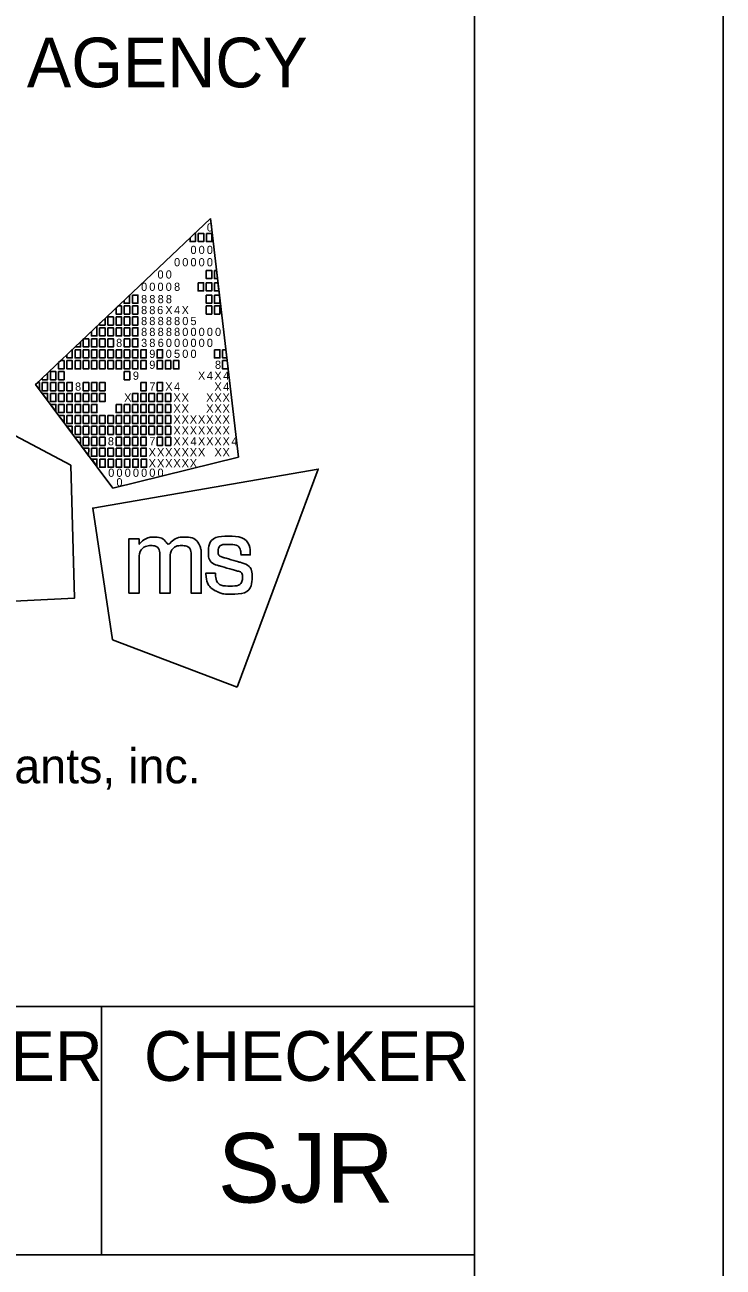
# Model space of a CAD drawing. Extents: x 0 to 34, y 0 to 22.
# Drawn here: x 32.596 to 34, y 2.475 to 4.976 of the extents above; entities that cross this region are included whole.
import ezdxf

# ---------------------------------------------------------------- set-up
doc = ezdxf.new("R2010")
doc.units = 0
for name, color, linetype in [('SH_Border', 7, 'Continuous'), ('SH_Cut_Line', 7, 'Continuous'), ('SH_Data', 7, 'Continuous'), ('SH_Text', 7, 'Continuous')]:
    doc.layers.add(name, color=color, linetype=linetype)

msp = doc.modelspace()

# ---------------------------------------------------------------- linework, layer by layer
at = {"layer": 'SH_Border'}
for p, q in [((32, 3), (33.5, 3)), ((32.75, 3), (32.75, 2.5)), ((32, 2.5), (33.5, 2.5))]:
    msp.add_line(p, q, dxfattribs=at)
msp.add_lwpolyline([(1.5, 21.5), (33.5, 21.5), (33.5, 0.5), (1.5, 0.5)], close=True, dxfattribs=at)
at = {"layer": 'SH_Cut_Line'}
msp.add_lwpolyline([(0, 0), (34, 0), (34, 22), (0, 22)], close=True, dxfattribs=at)
at = {"layer": 'SH_Data'}
msp.add_line((32.75, 4), (32.75, 4), dxfattribs=at)
at = {"layer": 'SH_Text'}
for p, q in [((32.6175, 4.2519), (32.9688, 4.5861)), ((32.9688, 4.5861), (32.9688, 4.5861)), ((32.9688, 4.5861), (33.0253, 4.1052)), ((32.773, 4.043), (32.6175, 4.2519)), ((33.0253, 4.1052), (32.773, 4.043))]:
    msp.add_line(p, q, dxfattribs=at)
for points in [[(32.9279, 4.5472), (32.9369, 4.5558), (32.9389, 4.5558), (32.9389, 4.5393), (32.9279, 4.5393)], [(32.9444, 4.5558), (32.9554, 4.5558), (32.9554, 4.5393), (32.9444, 4.5393)], [(32.9609, 4.5558), (32.9719, 4.5558), (32.9719, 4.5393), (32.9609, 4.5393)], [(32.9606, 4.4815), (32.9716, 4.4815), (32.9716, 4.465), (32.9606, 4.465)], [(32.9771, 4.4815), (32.9811, 4.4815), (32.983, 4.465), (32.9771, 4.465)], [(32.9441, 4.4567), (32.9551, 4.4567), (32.9551, 4.4402), (32.9441, 4.4402)], [(32.9606, 4.4567), (32.9716, 4.4567), (32.9716, 4.4402), (32.9606, 4.4402)], [(32.9771, 4.4567), (32.984, 4.4567), (32.9859, 4.4402), (32.9771, 4.4402)], [(32.7953, 4.4211), (32.8064, 4.4316), (32.8064, 4.4154), (32.7953, 4.4154)], [(32.8123, 4.4319), (32.8233, 4.4319), (32.8233, 4.4154), (32.8123, 4.4154)], [(32.9606, 4.4319), (32.9716, 4.4319), (32.9716, 4.4154), (32.9606, 4.4154)], [(32.9771, 4.4319), (32.9869, 4.4319), (32.9881, 4.4218), (32.9881, 4.4154), (32.9771, 4.4154)], [(32.7958, 4.4099), (32.8068, 4.4099), (32.8068, 4.3934), (32.7958, 4.3934)], [(32.8123, 4.4099), (32.8233, 4.4099), (32.8233, 4.3934), (32.8123, 4.3934)], [(32.9606, 4.4099), (32.9716, 4.4099), (32.9716, 4.3934), (32.9606, 4.3934)], [(32.9771, 4.4099), (32.9881, 4.4099), (32.9881, 4.3934), (32.9771, 4.3934)], [(32.7627, 4.3879), (32.7737, 4.3879), (32.7737, 4.3714), (32.7627, 4.3714)], [(32.7793, 4.3879), (32.7903, 4.3879), (32.7903, 4.3714), (32.7793, 4.3714)], [(32.7958, 4.3879), (32.8068, 4.3879), (32.8068, 4.3714), (32.7958, 4.3714)], [(32.8123, 4.3879), (32.8233, 4.3879), (32.8233, 4.3714), (32.8123, 4.3714)], [(32.7462, 4.3659), (32.7572, 4.3659), (32.7572, 4.3494), (32.7462, 4.3494)], [(32.7627, 4.3659), (32.7737, 4.3659), (32.7737, 4.3494), (32.7627, 4.3494)], [(32.7793, 4.3659), (32.7903, 4.3659), (32.7903, 4.3494), (32.7793, 4.3494)], [(32.7958, 4.3659), (32.8068, 4.3659), (32.8068, 4.3494), (32.7958, 4.3494)], [(32.8123, 4.3659), (32.8233, 4.3659), (32.8233, 4.3494), (32.8123, 4.3494)], [(32.7297, 4.3439), (32.7407, 4.3439), (32.7407, 4.3273), (32.7297, 4.3273)], [(32.7462, 4.3439), (32.7572, 4.3439), (32.7572, 4.3273), (32.7462, 4.3273)], [(32.7627, 4.3439), (32.7737, 4.3439), (32.7737, 4.3273), (32.7627, 4.3273)], [(32.7958, 4.3439), (32.8068, 4.3439), (32.8068, 4.3273), (32.7958, 4.3273)], [(32.8123, 4.3439), (32.8233, 4.3439), (32.8233, 4.3273), (32.8123, 4.3273)], [(32.6967, 4.3218), (32.7077, 4.3218), (32.7077, 4.3053), (32.6967, 4.3053)], [(32.7132, 4.3218), (32.7242, 4.3218), (32.7242, 4.3053), (32.7132, 4.3053)], [(32.7297, 4.3218), (32.7407, 4.3218), (32.7407, 4.3053), (32.7297, 4.3053)], [(32.7462, 4.3218), (32.7572, 4.3218), (32.7572, 4.3053), (32.7462, 4.3053)], [(32.7627, 4.3218), (32.7737, 4.3218), (32.7737, 4.3053), (32.7627, 4.3053)], [(32.7793, 4.3218), (32.7903, 4.3218), (32.7903, 4.3053), (32.7793, 4.3053)], [(32.7958, 4.3218), (32.8068, 4.3218), (32.8068, 4.3053), (32.7958, 4.3053)], [(32.8123, 4.3218), (32.8233, 4.3218), (32.8233, 4.3053), (32.8123, 4.3053)], [(32.8288, 4.3218), (32.8398, 4.3218), (32.8398, 4.3053), (32.8288, 4.3053)], [(32.8618, 4.3218), (32.8728, 4.3218), (32.8728, 4.3053), (32.8618, 4.3053)], [(32.9771, 4.3218), (32.9881, 4.3218), (32.9881, 4.3053), (32.9771, 4.3053)], [(32.9935, 4.3218), (32.9998, 4.3218), (33.0018, 4.3053), (32.9935, 4.3053)], [(32.6471, 4.2778), (32.6581, 4.2778), (32.6581, 4.2613), (32.6471, 4.2613)], [(32.6637, 4.2778), (32.6747, 4.2778), (32.6747, 4.2613), (32.6637, 4.2613)], [(32.6802, 4.2998), (32.6912, 4.2998), (32.6912, 4.2833), (32.6802, 4.2833)], [(32.6967, 4.2998), (32.7077, 4.2998), (32.7077, 4.2833), (32.6967, 4.2833)], [(32.7132, 4.2998), (32.7242, 4.2998), (32.7242, 4.2833), (32.7132, 4.2833)], [(32.7297, 4.2998), (32.7407, 4.2998), (32.7407, 4.2833), (32.7297, 4.2833)], [(32.7462, 4.2998), (32.7572, 4.2998), (32.7572, 4.2833), (32.7462, 4.2833)], [(32.7627, 4.2998), (32.7737, 4.2998), (32.7737, 4.2833), (32.7627, 4.2833)], [(32.7793, 4.2998), (32.7903, 4.2998), (32.7903, 4.2833), (32.7793, 4.2833)], [(32.7958, 4.2998), (32.8068, 4.2998), (32.8068, 4.2833), (32.7958, 4.2833)], [(32.7958, 4.2778), (32.8068, 4.2778), (32.8068, 4.2613), (32.7958, 4.2613)], [(32.8123, 4.2998), (32.8233, 4.2998), (32.8233, 4.2833), (32.8123, 4.2833)], [(32.8288, 4.2998), (32.8398, 4.2998), (32.8398, 4.2833), (32.8288, 4.2833)], [(32.8618, 4.2998), (32.8728, 4.2998), (32.8728, 4.2833), (32.8618, 4.2833)], [(32.8783, 4.2998), (32.8893, 4.2998), (32.8893, 4.2833), (32.8783, 4.2833)], [(32.8947, 4.2998), (32.9057, 4.2998), (32.9057, 4.2833), (32.8947, 4.2833)], [(32.9935, 4.2998), (33.0024, 4.2998), (33.0044, 4.2833), (32.9935, 4.2833)], [(32.6306, 4.2558), (32.6416, 4.2558), (32.6416, 4.2393), (32.6306, 4.2393)], [(32.6471, 4.2558), (32.6581, 4.2558), (32.6581, 4.2393), (32.6471, 4.2393)], [(32.6637, 4.2558), (32.6747, 4.2558), (32.6747, 4.2393), (32.6637, 4.2393)], [(32.6802, 4.2558), (32.6912, 4.2558), (32.6912, 4.2393), (32.6802, 4.2393)], [(32.7132, 4.2558), (32.7242, 4.2558), (32.7242, 4.2393), (32.7132, 4.2393)], [(32.7297, 4.2558), (32.7407, 4.2558), (32.7407, 4.2393), (32.7297, 4.2393)], [(32.7462, 4.2558), (32.7572, 4.2558), (32.7572, 4.2393), (32.7462, 4.2393)], [(32.8288, 4.2558), (32.8398, 4.2558), (32.8398, 4.2393), (32.8288, 4.2393)], [(32.8618, 4.2558), (32.8728, 4.2558), (32.8728, 4.2393), (32.8618, 4.2393)], [(32.6306, 4.2338), (32.6416, 4.2338), (32.6416, 4.22)], [(32.6471, 4.2338), (32.6581, 4.2338), (32.6581, 4.2173), (32.6471, 4.2173)], [(32.6637, 4.2338), (32.6747, 4.2338), (32.6747, 4.2173), (32.6637, 4.2173)], [(32.6802, 4.2338), (32.6912, 4.2338), (32.6912, 4.2173), (32.6802, 4.2173)], [(32.6967, 4.2338), (32.7077, 4.2338), (32.7077, 4.2173), (32.6967, 4.2173)], [(32.7132, 4.2338), (32.7242, 4.2338), (32.7242, 4.2173), (32.7132, 4.2173)], [(32.7297, 4.2338), (32.7407, 4.2338), (32.7407, 4.2173), (32.7297, 4.2173)], [(32.7462, 4.2338), (32.7572, 4.2338), (32.7572, 4.2173), (32.7462, 4.2173)], [(32.8123, 4.2338), (32.8233, 4.2338), (32.8233, 4.2173), (32.8123, 4.2173)], [(32.8288, 4.2338), (32.8398, 4.2338), (32.8398, 4.2173), (32.8288, 4.2173)], [(32.8453, 4.2338), (32.8563, 4.2338), (32.8563, 4.2173), (32.8453, 4.2173)], [(32.8618, 4.2338), (32.8728, 4.2338), (32.8728, 4.2173), (32.8618, 4.2173)], [(32.8783, 4.2338), (32.8893, 4.2338), (32.8893, 4.2173), (32.8783, 4.2173)], [(32.6471, 4.2117), (32.6581, 4.2117), (32.6581, 4.198)], [(32.6637, 4.2117), (32.6747, 4.2117), (32.6747, 4.1952), (32.6637, 4.1952)], [(32.6802, 4.2117), (32.6912, 4.2117), (32.6912, 4.1952), (32.6802, 4.1952)], [(32.6967, 4.2117), (32.7077, 4.2117), (32.7077, 4.1952), (32.6967, 4.1952)], [(32.7132, 4.2117), (32.7242, 4.2117), (32.7242, 4.1952), (32.7132, 4.1952)], [(32.7297, 4.2117), (32.7407, 4.2117), (32.7407, 4.1952), (32.7297, 4.1952)], [(32.7793, 4.2117), (32.7903, 4.2117), (32.7903, 4.1952), (32.7793, 4.1952)], [(32.7958, 4.2117), (32.8068, 4.2117), (32.8068, 4.1952), (32.7958, 4.1952)], [(32.8123, 4.2117), (32.8233, 4.2117), (32.8233, 4.1952), (32.8123, 4.1952)], [(32.8288, 4.2117), (32.8398, 4.2117), (32.8398, 4.1952), (32.8288, 4.1952)], [(32.8453, 4.2117), (32.8563, 4.2117), (32.8563, 4.1952), (32.8453, 4.1952)], [(32.8618, 4.2117), (32.8728, 4.2117), (32.8728, 4.1952), (32.8618, 4.1952)], [(32.8783, 4.2117), (32.8893, 4.2117), (32.8893, 4.1952), (32.8783, 4.1952)], [(32.6637, 4.1897), (32.6747, 4.1897), (32.6747, 4.176)], [(32.6747, 4.1897), (32.6747, 4.1897), (32.6747, 4.1897)], [(32.6802, 4.1897), (32.6912, 4.1897), (32.6912, 4.1732), (32.6802, 4.1732)], [(32.6967, 4.1897), (32.7077, 4.1897), (32.7077, 4.1732), (32.6967, 4.1732)], [(32.7132, 4.1897), (32.7242, 4.1897), (32.7242, 4.1732), (32.7132, 4.1732)], [(32.7297, 4.1897), (32.7407, 4.1897), (32.7407, 4.1732), (32.7297, 4.1732)], [(32.7462, 4.1897), (32.7572, 4.1897), (32.7572, 4.1732), (32.7462, 4.1732)], [(32.7627, 4.1897), (32.7737, 4.1897), (32.7737, 4.1732), (32.7627, 4.1732)], [(32.7793, 4.1897), (32.7903, 4.1897), (32.7903, 4.1732), (32.7793, 4.1732)], [(32.7958, 4.1897), (32.8068, 4.1897), (32.8068, 4.1732), (32.7958, 4.1732)], [(32.8123, 4.1897), (32.8233, 4.1897), (32.8233, 4.1732), (32.8123, 4.1732)], [(32.8288, 4.1897), (32.8398, 4.1897), (32.8398, 4.1732), (32.8288, 4.1732)], [(32.8453, 4.1897), (32.8563, 4.1897), (32.8563, 4.1732), (32.8453, 4.1732)], [(32.8618, 4.1897), (32.8728, 4.1897), (32.8728, 4.1732), (32.8618, 4.1732)], [(32.8783, 4.1897), (32.8893, 4.1897), (32.8893, 4.1732), (32.8783, 4.1732)], [(32.6802, 4.1677), (32.6912, 4.1677), (32.6912, 4.154)], [(32.6967, 4.1677), (32.7077, 4.1677), (32.7077, 4.1512), (32.6967, 4.1512)], [(32.7132, 4.1677), (32.7242, 4.1677), (32.7242, 4.1512), (32.7132, 4.1512)], [(32.7297, 4.1677), (32.7407, 4.1677), (32.7407, 4.1512), (32.7297, 4.1512)], [(32.7462, 4.1677), (32.7572, 4.1677), (32.7572, 4.1512), (32.7462, 4.1512)], [(32.7627, 4.1677), (32.7737, 4.1677), (32.7737, 4.1512), (32.7627, 4.1512)], [(32.7793, 4.1677), (32.7903, 4.1677), (32.7903, 4.1512), (32.7793, 4.1512)], [(32.7958, 4.1677), (32.8068, 4.1677), (32.8068, 4.1512), (32.7958, 4.1512)], [(32.8123, 4.1677), (32.8233, 4.1677), (32.8233, 4.1512), (32.8123, 4.1512)], [(32.8288, 4.1677), (32.8398, 4.1677), (32.8398, 4.1512), (32.8288, 4.1512)], [(32.8453, 4.1677), (32.8563, 4.1677), (32.8563, 4.1512), (32.8453, 4.1512)], [(32.8618, 4.1677), (32.8728, 4.1677), (32.8728, 4.1512), (32.8618, 4.1512)], [(32.8783, 4.1677), (32.8893, 4.1677), (32.8893, 4.1512), (32.8783, 4.1512)], [(32.7077, 4.1305), (32.6965, 4.1457), (32.7077, 4.1457)], [(32.7132, 4.1457), (32.7242, 4.1457), (32.7242, 4.1292), (32.7132, 4.1292)], [(32.7297, 4.1457), (32.7407, 4.1457), (32.7407, 4.1292), (32.7297, 4.1292)], [(32.7462, 4.1457), (32.7572, 4.1457), (32.7572, 4.1292), (32.7462, 4.1292)], [(32.7793, 4.1457), (32.7903, 4.1457), (32.7903, 4.1292), (32.7793, 4.1292)], [(32.7958, 4.1457), (32.8068, 4.1457), (32.8068, 4.1292), (32.7958, 4.1292)], [(32.8123, 4.1457), (32.8233, 4.1457), (32.8233, 4.1292), (32.8123, 4.1292)], [(32.8288, 4.1457), (32.8398, 4.1457), (32.8398, 4.1292), (32.8288, 4.1292)], [(32.8618, 4.1457), (32.8728, 4.1457), (32.8728, 4.1292), (32.8618, 4.1292)], [(32.8783, 4.1457), (32.8893, 4.1457), (32.8893, 4.1292), (32.8783, 4.1292)], [(32.724, 4.1082), (32.7132, 4.1237), (32.7242, 4.1237)], [(32.7297, 4.1237), (32.7407, 4.1237), (32.7407, 4.1072), (32.7297, 4.1072)], [(32.7302, 4.1017), (32.7407, 4.1017), (32.7408, 4.0875)], [(32.7462, 4.1237), (32.7572, 4.1237), (32.7572, 4.1072), (32.7462, 4.1072)], [(32.7463, 4.1017), (32.7573, 4.1017), (32.7573, 4.0852), (32.7463, 4.0852)], [(32.7627, 4.1237), (32.7737, 4.1237), (32.7737, 4.1072), (32.7627, 4.1072)], [(32.763, 4.1017), (32.774, 4.1017), (32.774, 4.0852), (32.763, 4.0852)], [(32.7793, 4.1237), (32.7903, 4.1237), (32.7903, 4.1072), (32.7793, 4.1072)], [(32.7794, 4.1017), (32.7904, 4.1017), (32.7904, 4.0852), (32.7794, 4.0852)], [(32.7958, 4.1237), (32.8068, 4.1237), (32.8068, 4.1072), (32.7958, 4.1072)], [(32.796, 4.1017), (32.807, 4.1017), (32.807, 4.0852), (32.796, 4.0852)], [(32.8123, 4.1237), (32.8233, 4.1237), (32.8233, 4.1072), (32.8123, 4.1072)], [(32.8129, 4.1017), (32.8239, 4.1017), (32.8239, 4.0851), (32.8129, 4.0851)], [(32.8288, 4.1237), (32.8398, 4.1237), (32.8398, 4.1072), (32.8288, 4.1072)], [(32.8296, 4.1017), (32.8406, 4.1017), (32.8406, 4.0851), (32.8296, 4.0851)]]:
    msp.add_lwpolyline(points, close=True, dxfattribs=at)
for points in [[(32.7903, 4.4099), (32.7836, 4.4099), (32.7793, 4.4058), (32.7793, 4.3934), (32.7903, 4.3934), (32.7903, 4.4099)], [(32.7572, 4.3849), (32.7462, 4.3744), (32.7462, 4.3714), (32.7572, 4.3714), (32.7572, 4.3849)], [(32.7407, 4.3691), (32.7297, 4.3587), (32.7297, 4.3494), (32.7407, 4.3494), (32.7407, 4.3691)], [(32.7077, 4.3377), (32.6968, 4.3273), (32.7077, 4.3273), (32.7077, 4.3377)], [(32.7242, 4.3439), (32.7141, 4.3439), (32.7132, 4.343), (32.7132, 4.3273), (32.7242, 4.3273), (32.7242, 4.3439)], [(32.6912, 4.322), (32.6802, 4.3115), (32.6802, 4.3053), (32.6912, 4.3053), (32.6912, 4.322)], [(32.6747, 4.2998), (32.6679, 4.2998), (32.6637, 4.2958), (32.6637, 4.2833), (32.6747, 4.2833), (32.6747, 4.2998)], [(32.6251, 4.2558), (32.6216, 4.2558), (32.6175, 4.2519), (32.6251, 4.2417), (32.6251, 4.2558)], [(32.6416, 4.2749), (32.6306, 4.2644), (32.6306, 4.2613), (32.6416, 4.2613), (32.6416, 4.2749)], [(32.4512, 4.2149), (32.2359, 3.7988), (32.6956, 3.8215), (32.6884, 4.0892), (32.4512, 4.2149)], [(33.0229, 3.6422), (33.1859, 4.0814), (32.7324, 4.0029), (32.7722, 3.7381), (33.0229, 3.6422)]]:
    msp.add_lwpolyline(points, dxfattribs=at)
for points in [[(32.8048, 3.8315), (32.8048, 3.8315), (32.8048, 3.9409), (32.8048, 3.9409), (32.8048, 3.9409), (32.8255, 3.9409), (32.8255, 3.9409), (32.8255, 3.9409), (32.8255, 3.9297), (32.8255, 3.9297), (32.8346, 3.9399), (32.8457, 3.9445), (32.8555, 3.9445), (32.8688, 3.9445), (32.8791, 3.9372), (32.8837, 3.9266), (32.8915, 3.9381), (32.905, 3.9446), (32.9166, 3.9446), (32.9325, 3.9446), (32.9451, 3.935), (32.9494, 3.9213), (32.9494, 3.9212), (32.9494, 3.9212), (32.9494, 3.9212), (32.9501, 3.919), (32.9506, 3.9172), (32.9506, 3.9071), (32.9506, 3.9071), (32.9506, 3.8314), (32.9506, 3.8314), (32.9506, 3.8314), (32.9303, 3.8314), (32.9303, 3.8314), (32.9303, 3.8314), (32.9303, 3.9048), (32.9303, 3.9048), (32.9303, 3.9201), (32.9219, 3.9274), (32.911, 3.9274), (32.8995, 3.9274), (32.8879, 3.9171), (32.8879, 3.9001), (32.8879, 3.9001), (32.8879, 3.8315), (32.8879, 3.8315), (32.8879, 3.8315), (32.8674, 3.8315), (32.8674, 3.8315), (32.8674, 3.8315), (32.8674, 3.9059), (32.8674, 3.9059), (32.8674, 3.9203), (32.8588, 3.9274), (32.8496, 3.9274), (32.8384, 3.9274), (32.8254, 3.917), (32.8254, 3.8962), (32.8254, 3.8962), (32.8254, 3.8315), (32.8254, 3.8315), (32.8254, 3.8315), (32.8048, 3.8315), (32.8048, 3.8315)], [(32.9595, 3.8709), (32.9595, 3.8709), (32.9595, 3.8717), (32.9595, 3.8717), (32.9595, 3.8717), (32.9603, 3.8717), (32.9603, 3.8717), (32.9603, 3.8717), (32.9783, 3.8717), (32.9783, 3.8717), (32.9783, 3.8717), (32.9789, 3.8717), (32.9789, 3.8717), (32.9789, 3.8717), (32.979, 3.871), (32.979, 3.871), (32.9803, 3.8554), (32.9887, 3.846), (33.009, 3.846), (33.0273, 3.846), (33.0333, 3.8554), (33.0333, 3.8631), (33.0333, 3.8732), (33.0256, 3.8758), (33.0175, 3.878), (33.0175, 3.878), (32.987, 3.8867), (32.987, 3.8867), (32.972, 3.8909), (32.9648, 3.9019), (32.9648, 3.9142), (32.9648, 3.9303), (32.9768, 3.9462), (33.0052, 3.9462), (33.0348, 3.9462), (33.0489, 3.9285), (33.0489, 3.9095), (33.0489, 3.9095), (33.0489, 3.9087), (33.0489, 3.9087), (33.0489, 3.9087), (33.0482, 3.9087), (33.0482, 3.9087), (33.0482, 3.9087), (33.0312, 3.9087), (33.0312, 3.9087), (33.0312, 3.9087), (33.0305, 3.9087), (33.0305, 3.9087), (33.0305, 3.9087), (33.0305, 3.9094), (33.0305, 3.9094), (33.0301, 3.9208), (33.0226, 3.93), (33.0056, 3.93), (32.9891, 3.93), (32.9843, 3.9218), (32.9843, 3.9157), (32.9843, 3.9108), (32.9869, 3.9059), (32.9959, 3.9033), (32.9959, 3.9033), (33.0255, 3.8948), (33.0255, 3.8948), (33.0462, 3.8889), (33.0527, 3.8777), (33.0527, 3.8639), (33.0527, 3.8462), (33.041, 3.8298), (33.0087, 3.8298), (32.9952, 3.8298), (32.9877, 3.8321), (32.9823, 3.8348), (32.969, 3.8414), (32.9609, 3.8536), (32.9595, 3.8709)]]:
    msp.add_open_spline(points, degree=3, dxfattribs=at)

# ---------------------------------------------------------------- texts
at = {"layer": 'SH_Border'}
msp.add_text('ms consultants, inc.', height=0.07, rotation=360, dxfattribs=at).set_placement((32.1273, 3.4489))
at = {"layer": 'SH_Data'}
for s, height, p in [('DESIGN AGENCY', 0.1, (32.05, 4.85)), ('DESIGNER', 0.1, (32.054, 2.85)), ('CHECKER', 0.1, (32.8352, 2.85)), ('SJR', 0.14, (32.9839, 2.605))]:
    msp.add_text(s, height=height, dxfattribs=at).set_placement(p)
at = {"layer": 'SH_Text'}
for s, p in [('0', (32.9617, 4.5597)), ('0', (32.9288, 4.5145)), ('0', (32.9452, 4.5145)), ('0', (32.9617, 4.5145)), ('0', (32.8958, 4.4897)), ('0', (32.9123, 4.4897)), ('0', (32.9288, 4.4897)), ('0', (32.9452, 4.4897)), ('0', (32.9617, 4.4897)), ('0', (32.8625, 4.465)), ('0', (32.879, 4.465)), ('0', (32.8295, 4.4402)), ('0', (32.846, 4.4402)), ('0', (32.8625, 4.4402)), ('0', (32.879, 4.4402)), ('8', (32.8958, 4.4402)), ('8', (32.8295, 4.4154)), ('8', (32.846, 4.4154)), ('8', (32.8628, 4.4154)), ('8', (32.8793, 4.4154)), ('8', (32.8295, 4.3934)), ('8', (32.846, 4.3934)), ('6', (32.8618, 4.3934)), ('X', (32.8781, 4.3934)), ('4', (32.8958, 4.3934)), ('X', (32.911, 4.3934)), ('8', (32.8295, 4.3713)), ('8', (32.846, 4.3713)), ('8', (32.8628, 4.3713)), ('8', (32.8794, 4.3713)), ('8', (32.8958, 4.3713)), ('0', (32.9123, 4.3713)), ('5', (32.9287, 4.3713)), ('8', (32.8295, 4.3494)), ('8', (32.846, 4.3494)), ('8', (32.8628, 4.3494)), ('8', (32.8794, 4.3494)), ('8', (32.8958, 4.3494)), ('0', (32.9123, 4.3494)), ('0', (32.9288, 4.3494)), ('0', (32.9452, 4.3494)), ('0', (32.9617, 4.3494)), ('0', (32.9782, 4.3494)), ('8', (32.7793, 4.3273)), ('3', (32.8295, 4.3273)), ('8', (32.846, 4.3273)), ('6', (32.8629, 4.3273)), ('0', (32.8793, 4.3273)), ('0', (32.8958, 4.3273)), ('0', (32.9123, 4.3273)), ('0', (32.9288, 4.3273)), ('0', (32.9452, 4.3273)), ('0', (32.9617, 4.3273)), ('9', (32.846, 4.3053)), ('0', (32.879, 4.3053)), ('5', (32.8957, 4.3053)), ('0', (32.9123, 4.3053)), ('0', (32.9288, 4.3053)), ('9', (32.813, 4.2613)), ('9', (32.846, 4.2833)), ('X', (32.9439, 4.2613)), ('4', (32.9617, 4.2613)), ('X', (32.9769, 4.2613)), ('8', (32.9781, 4.2833)), ('4', (32.9946, 4.2613)), ('8', (32.6967, 4.2393)), ('7', (32.846, 4.2393)), ('X', (32.8781, 4.2393)), ('4', (32.8958, 4.2393)), ('X', (32.9769, 4.2393)), ('4', (32.9946, 4.2393)), ('X', (32.7955, 4.2173)), ('X', (32.8945, 4.2173)), ('X', (32.911, 4.2173)), ('X', (32.9604, 4.2173)), ('X', (32.9769, 4.2173)), ('X', (32.9933, 4.2173)), ('X', (32.8945, 4.1952)), ('X', (32.911, 4.1952)), ('X', (32.9604, 4.1952)), ('X', (32.9769, 4.1952)), ('X', (32.9933, 4.1952)), ('X', (32.8945, 4.1732)), ('X', (32.911, 4.1732)), ('X', (32.9274, 4.1732)), ('X', (32.9439, 4.1732)), ('X', (32.9604, 4.1732)), ('X', (32.9769, 4.1732)), ('X', (32.9933, 4.1732)), ('X', (32.8945, 4.1512)), ('X', (32.911, 4.1512)), ('X', (32.9274, 4.1512)), ('X', (32.9439, 4.1512)), ('X', (32.9604, 4.1512)), ('X', (32.9769, 4.1512)), ('X', (32.9933, 4.1512)), ('8', (32.7627, 4.1292)), ('7', (32.846, 4.1292)), ('X', (32.8945, 4.1292)), ('X', (32.911, 4.1292)), ('4', (32.9288, 4.1292)), ('X', (32.9439, 4.1292)), ('X', (32.9604, 4.1292)), ('X', (32.9769, 4.1292)), ('X', (32.9933, 4.1292)), ('4', (33.0111, 4.1292)), ('X', (32.8447, 4.1072)), ('X', (32.8447, 4.0851)), ('X', (32.8616, 4.1072)), ('X', (32.8616, 4.0851)), ('X', (32.878, 4.1072)), ('X', (32.878, 4.0851)), ('X', (32.8945, 4.1072)), ('X', (32.8945, 4.0851)), ('X', (32.911, 4.1072)), ('X', (32.911, 4.0851)), ('X', (32.9274, 4.1072)), ('X', (32.9274, 4.0851)), ('X', (32.9439, 4.1072)), ('X', (32.9771, 4.1072)), ('X', (32.9933, 4.1072)), ('0', (32.7634, 4.0659)), ('0', (32.7799, 4.0659)), ('0', (32.7965, 4.0659)), ('0', (32.813, 4.0659)), ('0', (32.8295, 4.0659)), ('0', (32.846, 4.0659)), ('0', (32.8625, 4.0659)), ('0', (32.7799, 4.0467))]:
    msp.add_text(s, height=0.0165, rotation=360, dxfattribs=at).set_placement(p)

doc.saveas('drawing.dxf')
